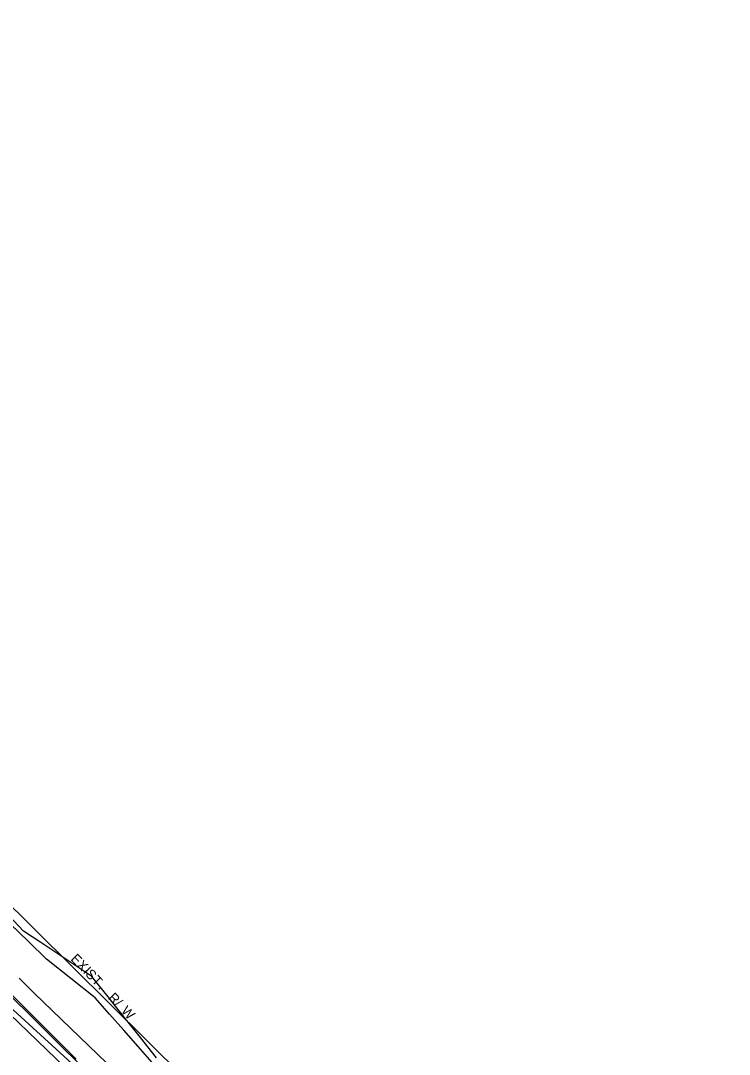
# Model space of a CAD drawing. Extents: x 1660112 to 1662239, y 668919 to 671377.
# Drawn here: x 1660964 to 1661405, y 670527 to 671170 of the extents above; entities that cross this region are included whole.
import ezdxf

# ---------------------------------------------------------------- set-up
doc = ezdxf.new("R2010")
doc.units = 0
for name, color, linetype in [('R_Annotation', 7, 'Continuous'), ('S_BASELINE', 7, 'Continuous'), ('S_DITCHLINE', 7, 'Continuous'), ('S_EDGE_PAVEMENT', 7, 'Continuous'), ('S_EXIST_ROW', 7, 'Continuous'), ('S_EXISTING_ALIGNMENT', 7, 'Continuous'), ('S_PAVEMENT_CROWN', 7, 'Continuous')]:
    doc.layers.add(name, color=color, linetype=linetype)

msp = doc.modelspace()

# ---------------------------------------------------------------- linework, layer by layer
at = {"layer": 'S_BASELINE'}
msp.add_line((1660813.76, 670687.35), (1661335.19, 670212.07), dxfattribs=at)
at = {"layer": 'S_DITCHLINE'}
for points in [[(1661048.65, 670524.7), (1661038.6, 670537.35), (1661028.55, 670549.99), (1661018.5, 670562.64), (1661008.44, 670575.28), (1660997.82, 670582.34), (1660987.2, 670589.4), (1660976.58, 670596.46), (1660965.97, 670603.52), (1660956.84, 670613.17)], [(1661046, 670521.68), (1661037.13, 670531.76), (1661028.26, 670541.83), (1661019.39, 670551.9), (1661010.52, 670561.97), (1660995.35, 670573.96), (1660980.18, 670585.95), (1660968.92, 670597.02), (1660957.66, 670608.1)]]:
    msp.add_lwpolyline(points, dxfattribs=at)
at = {"layer": 'S_EDGE_PAVEMENT'}
for points in [[(1661017.49, 670521.66), (1661006.48, 670532.23), (1660989.54, 670548.58), (1660972.6, 670564.94), (1660963.23, 670574.29)], [(1660991.93, 670518.47), (1660974.69, 670535.16), (1660957.45, 670551.84)]]:
    msp.add_lwpolyline(points, dxfattribs=at)
at = {"layer": 'S_EXIST_ROW'}
msp.add_line((1661404.92, 670177.11), (1660401.45, 671169.67), dxfattribs=at)
at = {"layer": 'S_EXISTING_ALIGNMENT'}
msp.add_line((1661376.17, 670149.3), (1660373.32, 671141.23), dxfattribs=at)
at = {"layer": 'S_PAVEMENT_CROWN'}
msp.add_lwpolyline([(1660998.68, 670523.89), (1660981.9, 670540.69), (1660965.12, 670557.48), (1660955.88, 670566.56)], dxfattribs=at)

# ---------------------------------------------------------------- texts
at = {"layer": 'R_Annotation'}
for s, p in [('E', (1660994.84, 670585.83)), ('X', (1660998.58, 670581.96)), ('I', (1661002.58, 670577.81)), ('S', (1661003.96, 670576.39)), ('T', (1661007.9, 670572.31)), ('.', (1661011.97, 670568.09)), ('R', (1661018.17, 670561.67)), ('/', (1661022.11, 670557.59)), ('W', (1661026.18, 670553.38))]:
    msp.add_text(s, height=6, rotation=313.99934, dxfattribs=at).set_placement(p)

doc.saveas('drawing.dxf')
